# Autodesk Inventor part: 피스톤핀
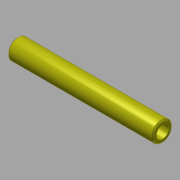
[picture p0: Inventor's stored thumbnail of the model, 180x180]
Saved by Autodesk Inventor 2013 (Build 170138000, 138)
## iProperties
Created: 2016-11
Part Number: 피스톤핀
Material: 강철, 탄소
Document SubType Name: Modeling
Designer: mduedu
Density: 7.87 g/cm^3
Mass: 24.6584 g
Surface Area: 42.7469 cm^2
Volume: 3.13322 cm^3
Author: mduedu
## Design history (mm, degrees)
sketch "스케치1"
  geometry: C1 r 2.5 at (0, 0); C2 r 4 at (0, 0); 1 further point
  constraints: 2 centre point, 2 coincident
  dimensions: "d0" = 5 diameter of C1; "d1" = 8 diameter of C2
extrude "돌출1" new body sketch "스케치1" stored distance "d2" = 58; taper "d3" = 0 deg
chamfer "모따기1" distance "d4" = 0.5; stored, may be unused: second distance "d5" = 2, angle "d6" = 45 deg
node "솔리드1"
